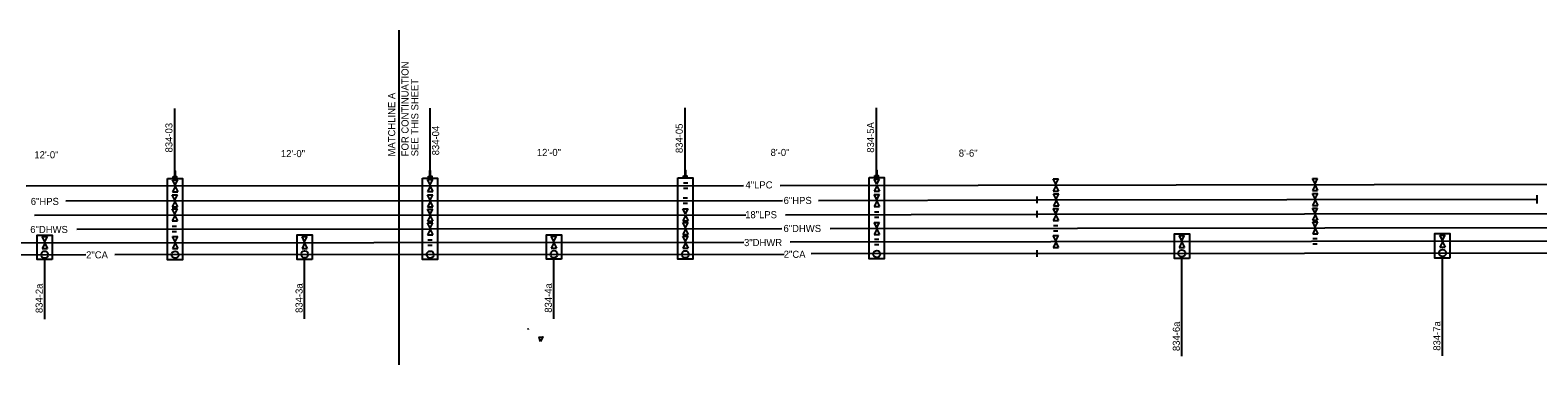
# Model space of a CAD drawing. Extents: x 9888 to 10178, y 10284 to 10314.
# Drawn here: x 10038.1 to 10109, y 10283.8 to 10299.5 of the extents above; entities that cross this region are included whole.
import ezdxf

# ---------------------------------------------------------------- set-up
doc = ezdxf.new("R2010")
doc.units = 0
for name, color, linetype in [('Level 51', 7, 'Continuous'), ('M-ANNO-NPLT', 7, 'Continuous'), ('M-CELL', 7, 'Continuous'), ('M-EQPM-N', 7, 'Continuous'), ('M-STEM-CONP', 7, 'Continuous'), ('M-STEM-CONP-N', 7, 'Continuous'), ('P-CMPA-PIPE', 7, 'Continuous'), ('P-CMPA-PIPE-N', 7, 'Continuous'), ('P-DOMW-HPIP-N', 7, 'Continuous')]:
    doc.layers.add(name, color=color, linetype=linetype)

msp = doc.modelspace()

# ---------------------------------------------------------------- linework, layer by layer
at = {"layer": 'Level 51'}
for p, q in [((10037.895, 10292.216), (10071.644, 10292.241)), ((10044.904, 10292.191), (10044.78, 10291.944)), ((10044.906, 10292.263), (10044.782, 10292.511)), ((10044.782, 10292.511), (10045.03, 10292.511)), ((10044.904, 10292.191), (10045.028, 10291.944)), ((10044.906, 10292.263), (10045.03, 10292.511)), ((10056.902, 10292.268), (10056.778, 10292.516)), ((10056.778, 10292.516), (10057.026, 10292.516)), ((10056.902, 10292.198), (10056.778, 10291.951)), ((10056.902, 10292.268), (10057.026, 10292.516)), ((10056.902, 10292.198), (10057.026, 10291.951)), ((10068.808, 10292.367), (10069.012, 10292.367)), ((10068.808, 10292.117), (10069.012, 10292.117)), ((10073.354, 10292.244), (10142.991, 10292.341)), ((10077.902, 10292.295), (10077.778, 10292.543)), ((10077.778, 10292.543), (10078.026, 10292.543)), ((10077.902, 10292.226), (10077.778, 10291.978)), ((10077.902, 10292.295), (10078.026, 10292.543)), ((10077.902, 10292.226), (10078.026, 10291.978)), ((10086.33, 10292.296), (10086.206, 10292.544)), ((10086.206, 10292.544), (10086.454, 10292.544)), ((10086.33, 10292.227), (10086.206, 10291.979)), ((10086.33, 10292.296), (10086.454, 10292.544)), ((10086.33, 10292.227), (10086.454, 10291.979)), ((10098.518, 10292.318), (10098.394, 10292.566)), ((10098.394, 10292.566), (10098.641, 10292.566)), ((10098.518, 10292.248), (10098.394, 10292.001)), ((10098.518, 10292.318), (10098.641, 10292.566)), ((10098.518, 10292.248), (10098.641, 10292.001)), ((10044.78, 10291.944), (10045.028, 10291.944)), ((10056.778, 10291.951), (10057.026, 10291.951)), ((10077.778, 10291.978), (10078.026, 10291.978)), ((10086.206, 10291.979), (10086.454, 10291.979)), ((10098.394, 10292.001), (10098.641, 10292.001))]:
    msp.add_line(p, q, dxfattribs=at)
at = {"layer": 'M-CELL'}
msp.add_line((10061.531, 10285.442), (10061.505, 10285.51), dxfattribs=at)
msp.add_lwpolyline([(10062.091, 10284.903), (10062.023, 10285.096), (10062.206, 10285.122), (10062.091, 10284.903)], dxfattribs=at)
at = {"layer": 'M-EQPM-N'}
for p, q in [((10044.895, 10292.567), (10044.895, 10295.862)), ((10056.895, 10292.583), (10056.895, 10295.877)), ((10068.895, 10292.598), (10068.895, 10295.893)), ((10077.895, 10292.61), (10077.895, 10295.893)), ((10038.769, 10285.947), (10038.769, 10288.75)), ((10050.995, 10285.957), (10050.995, 10288.759)), ((10062.72, 10285.965), (10062.72, 10288.768)), ((10092.256, 10284.211), (10092.256, 10288.809)), ((10104.51, 10284.228), (10104.51, 10288.825))]:
    msp.add_line(p, q, dxfattribs=at)
for points in [[(10044.542, 10292.567), (10045.247, 10292.567), (10045.247, 10288.743), (10044.542, 10288.743)], [(10056.542, 10292.583), (10057.247, 10292.583), (10057.247, 10288.759), (10056.542, 10288.759)], [(10068.542, 10292.598), (10069.247, 10292.598), (10069.247, 10288.775), (10068.542, 10288.775)], [(10077.542, 10292.61), (10078.247, 10292.61), (10078.247, 10288.786), (10077.542, 10288.786)], [(10039.121, 10288.75), (10038.416, 10288.75), (10038.416, 10289.905), (10039.121, 10289.905)], [(10051.347, 10288.759), (10050.642, 10288.759), (10050.642, 10289.914), (10051.347, 10289.914)], [(10063.072, 10288.768), (10062.367, 10288.768), (10062.367, 10289.923), (10063.072, 10289.923)], [(10092.609, 10288.809), (10091.904, 10288.809), (10091.904, 10289.964), (10092.609, 10289.964)], [(10104.863, 10288.825), (10104.158, 10288.825), (10104.158, 10289.98), (10104.863, 10289.98)]]:
    msp.add_lwpolyline(points, close=True, dxfattribs=at)
at = {"layer": 'M-STEM-CONP'}
for p, q in [((10055.423, 10299.548), (10055.423, 10283.799)), ((10039.757, 10291.511), (10073.463, 10291.537)), ((10044.896, 10291.555), (10044.772, 10291.803)), ((10044.772, 10291.803), (10045.02, 10291.803)), ((10044.896, 10291.485), (10044.772, 10291.238)), ((10044.896, 10291.555), (10045.02, 10291.803)), ((10044.896, 10291.485), (10045.02, 10291.238)), ((10056.902, 10291.545), (10056.778, 10291.793)), ((10056.778, 10291.793), (10057.026, 10291.793)), ((10056.902, 10291.476), (10056.778, 10291.228)), ((10056.902, 10291.545), (10057.026, 10291.793)), ((10056.902, 10291.476), (10057.026, 10291.228)), ((10068.801, 10291.66), (10069.005, 10291.66)), ((10068.801, 10291.41), (10069.005, 10291.41)), ((10075.157, 10291.539), (10085.43, 10291.561)), ((10077.902, 10291.573), (10077.778, 10291.82)), ((10077.778, 10291.82), (10078.026, 10291.82)), ((10077.902, 10291.503), (10077.778, 10291.255)), ((10077.902, 10291.573), (10078.026, 10291.82)), ((10077.902, 10291.503), (10078.026, 10291.255)), ((10085.43, 10291.718), (10085.43, 10291.404)), ((10085.43, 10291.561), (10108.945, 10291.592)), ((10086.337, 10291.597), (10086.213, 10291.845)), ((10086.213, 10291.845), (10086.461, 10291.845)), ((10086.337, 10291.528), (10086.213, 10291.28)), ((10086.337, 10291.597), (10086.461, 10291.845)), ((10086.337, 10291.528), (10086.461, 10291.28)), ((10098.524, 10291.613), (10098.4, 10291.861)), ((10098.4, 10291.861), (10098.648, 10291.861)), ((10098.524, 10291.544), (10098.4, 10291.296)), ((10098.524, 10291.613), (10098.648, 10291.861)), ((10098.524, 10291.544), (10098.648, 10291.296)), ((10108.945, 10291.788), (10108.945, 10291.397)), ((10044.772, 10291.238), (10045.02, 10291.238)), ((10056.778, 10291.228), (10057.026, 10291.228)), ((10077.778, 10291.255), (10078.026, 10291.255)), ((10085.43, 10290.887), (10145.023, 10290.966)), ((10086.329, 10290.914), (10086.205, 10291.162)), ((10086.205, 10291.162), (10086.453, 10291.162)), ((10086.329, 10290.845), (10086.205, 10290.597)), ((10086.213, 10291.28), (10086.461, 10291.28)), ((10086.329, 10290.914), (10086.453, 10291.162)), ((10086.329, 10290.845), (10086.453, 10290.597)), ((10098.4, 10291.296), (10098.648, 10291.296)), ((10086.205, 10290.597), (10086.453, 10290.597))]:
    msp.add_line(p, q, dxfattribs=at)
at = {"layer": 'M-STEM-CONP-N'}
for p, q in [((10038.287, 10290.836), (10071.748, 10290.86)), ((10044.896, 10290.892), (10044.772, 10291.139)), ((10044.772, 10291.139), (10045.02, 10291.139)), ((10044.896, 10290.822), (10044.772, 10290.574)), ((10044.896, 10290.892), (10045.02, 10291.139)), ((10044.896, 10290.822), (10045.02, 10290.574)), ((10056.902, 10290.882), (10056.778, 10291.13)), ((10056.778, 10291.13), (10057.026, 10291.13)), ((10056.902, 10290.813), (10056.778, 10290.565)), ((10056.902, 10290.882), (10057.026, 10291.13)), ((10056.902, 10290.813), (10057.026, 10290.565)), ((10068.902, 10290.898), (10068.778, 10291.145)), ((10068.778, 10291.145), (10069.026, 10291.145)), ((10068.902, 10290.828), (10068.778, 10290.58)), ((10068.902, 10290.898), (10069.026, 10291.145)), ((10068.902, 10290.828), (10069.026, 10290.58)), ((10073.617, 10290.863), (10085.43, 10290.887)), ((10077.792, 10291), (10077.996, 10291)), ((10077.792, 10290.75), (10077.996, 10290.75)), ((10085.43, 10291.04), (10085.43, 10290.727)), ((10098.516, 10290.93), (10098.392, 10291.178)), ((10098.392, 10291.178), (10098.64, 10291.178)), ((10098.516, 10290.861), (10098.392, 10290.613)), ((10098.516, 10290.93), (10098.64, 10291.178)), ((10098.516, 10290.861), (10098.64, 10290.613)), ((10044.772, 10290.574), (10045.02, 10290.574)), ((10056.778, 10290.565), (10057.026, 10290.565)), ((10068.778, 10290.58), (10069.026, 10290.58)), ((10098.392, 10290.613), (10098.64, 10290.613))]:
    msp.add_line(p, q, dxfattribs=at)
at = {"layer": 'P-CMPA-PIPE'}
msp.add_line((10085.43, 10289.037), (10145.135, 10289.116), dxfattribs=at)
for points in [[(10044.874, 10292.671), (10044.921, 10292.671), (10044.921, 10292.907), (10044.874, 10292.907)], [(10056.874, 10292.687), (10056.921, 10292.687), (10056.921, 10292.922), (10056.874, 10292.922)], [(10068.874, 10292.702), (10068.921, 10292.702), (10068.921, 10292.938), (10068.874, 10292.938)], [(10077.874, 10292.714), (10077.921, 10292.714), (10077.921, 10292.949), (10077.874, 10292.949)], [(10044.818, 10292.667), (10044.971, 10292.667), (10044.971, 10292.567), (10044.818, 10292.567)], [(10056.818, 10292.683), (10056.971, 10292.683), (10056.971, 10292.583), (10056.818, 10292.583)], [(10068.818, 10292.698), (10068.971, 10292.698), (10068.971, 10292.598), (10068.818, 10292.598)], [(10077.818, 10292.71), (10077.971, 10292.71), (10077.971, 10292.61), (10077.818, 10292.61)]]:
    msp.add_lwpolyline(points, close=True, dxfattribs=at)
at = {"layer": 'P-CMPA-PIPE-N'}
for p, q in [((9975.124, 10288.884), (10040.708, 10288.99)), ((10042.062, 10288.99), (10073.548, 10289.013)), ((10085.43, 10289.032), (10074.816, 10289.017)), ((10085.43, 10289.189), (10085.43, 10288.876))]:
    msp.add_line(p, q, dxfattribs=at)
for centre in [(10038.77, 10288.987), (10044.904, 10288.981), (10050.996, 10288.996), (10056.902, 10288.988), (10062.721, 10289.005), (10068.902, 10289.004), (10077.902, 10289.015), (10092.257, 10289.046), (10104.511, 10289.062)]:
    msp.add_circle(centre, 0.167, dxfattribs=at)
at = {"layer": 'P-DOMW-HPIP-N'}
for p, q in [((10040.286, 10290.183), (10073.438, 10290.208)), ((10044.769, 10290.33), (10044.973, 10290.33)), ((10044.769, 10290.08), (10044.973, 10290.08)), ((10056.902, 10290.23), (10056.778, 10290.478)), ((10056.778, 10290.478), (10057.026, 10290.478)), ((10056.902, 10290.161), (10056.778, 10289.913)), ((10056.902, 10290.23), (10057.026, 10290.478)), ((10056.902, 10290.161), (10057.026, 10289.913)), ((10068.902, 10290.246), (10068.778, 10290.494)), ((10068.778, 10290.494), (10069.026, 10290.494)), ((10068.902, 10290.176), (10068.778, 10289.929)), ((10068.902, 10290.246), (10069.026, 10290.494)), ((10068.902, 10290.176), (10069.026, 10289.929)), ((10075.709, 10290.221), (10164.791, 10290.337)), ((10077.902, 10290.258), (10077.778, 10290.505)), ((10077.778, 10290.505), (10078.026, 10290.505)), ((10077.902, 10290.188), (10077.778, 10289.94)), ((10077.902, 10290.258), (10078.026, 10290.505)), ((10077.902, 10290.188), (10078.026, 10289.94)), ((10086.224, 10290.36), (10086.428, 10290.36)), ((10086.224, 10290.11), (10086.428, 10290.11)), ((10098.531, 10290.28), (10098.407, 10290.528)), ((10098.407, 10290.528), (10098.654, 10290.528)), ((10098.531, 10290.21), (10098.407, 10289.963)), ((10098.531, 10290.28), (10098.654, 10290.528)), ((10098.531, 10290.21), (10098.654, 10289.963)), ((10036.846, 10289.542), (10071.655, 10289.568)), ((10038.77, 10289.584), (10038.646, 10289.832)), ((10038.646, 10289.832), (10038.894, 10289.832)), ((10038.77, 10289.515), (10038.646, 10289.267)), ((10038.77, 10289.584), (10038.894, 10289.832)), ((10038.77, 10289.515), (10038.894, 10289.267)), ((10044.904, 10289.59), (10044.78, 10289.838)), ((10044.78, 10289.838), (10045.028, 10289.838)), ((10044.904, 10289.521), (10044.78, 10289.273)), ((10044.904, 10289.59), (10045.028, 10289.838)), ((10044.904, 10289.521), (10045.028, 10289.273)), ((10050.996, 10289.594), (10050.872, 10289.841)), ((10050.872, 10289.841), (10051.12, 10289.841)), ((10050.996, 10289.524), (10050.872, 10289.276)), ((10050.996, 10289.594), (10051.12, 10289.841)), ((10050.996, 10289.524), (10051.12, 10289.276)), ((10056.778, 10289.913), (10057.026, 10289.913)), ((10056.791, 10289.684), (10056.995, 10289.684)), ((10056.791, 10289.434), (10056.995, 10289.434)), ((10062.721, 10289.602), (10062.598, 10289.85)), ((10062.598, 10289.85), (10062.845, 10289.85)), ((10062.721, 10289.533), (10062.598, 10289.285)), ((10062.598, 10289.285), (10062.845, 10289.285)), ((10062.721, 10289.602), (10062.845, 10289.85)), ((10062.721, 10289.533), (10062.845, 10289.285)), ((10068.778, 10289.929), (10069.026, 10289.929)), ((10068.914, 10289.601), (10068.79, 10289.849)), ((10068.79, 10289.849), (10069.038, 10289.849)), ((10068.914, 10289.531), (10068.79, 10289.284)), ((10068.79, 10289.284), (10069.038, 10289.284)), ((10068.914, 10289.601), (10069.038, 10289.849)), ((10068.914, 10289.531), (10069.038, 10289.284)), ((10073.838, 10289.582), (10160.703, 10289.695)), ((10077.778, 10289.94), (10078.026, 10289.94)), ((10077.791, 10289.711), (10077.995, 10289.711)), ((10077.791, 10289.461), (10077.995, 10289.461)), ((10086.331, 10289.633), (10086.207, 10289.881)), ((10086.207, 10289.881), (10086.455, 10289.881)), ((10086.331, 10289.564), (10086.207, 10289.316)), ((10086.207, 10289.316), (10086.455, 10289.316)), ((10086.331, 10289.633), (10086.455, 10289.881)), ((10086.331, 10289.564), (10086.455, 10289.316)), ((10092.258, 10289.643), (10092.134, 10289.891)), ((10092.134, 10289.891), (10092.382, 10289.891)), ((10092.258, 10289.574), (10092.134, 10289.326)), ((10092.134, 10289.326), (10092.382, 10289.326)), ((10092.258, 10289.643), (10092.382, 10289.891)), ((10092.258, 10289.574), (10092.382, 10289.326)), ((10098.407, 10289.963), (10098.654, 10289.963)), ((10098.416, 10289.737), (10098.62, 10289.737)), ((10098.416, 10289.487), (10098.62, 10289.487)), ((10104.512, 10289.659), (10104.388, 10289.907)), ((10104.388, 10289.907), (10104.636, 10289.907)), ((10104.512, 10289.59), (10104.388, 10289.342)), ((10104.388, 10289.342), (10104.636, 10289.342)), ((10104.512, 10289.659), (10104.636, 10289.907)), ((10104.512, 10289.59), (10104.636, 10289.342)), ((10038.646, 10289.267), (10038.894, 10289.267)), ((10044.78, 10289.273), (10045.028, 10289.273)), ((10050.872, 10289.276), (10051.12, 10289.276))]:
    msp.add_line(p, q, dxfattribs=at)

# ---------------------------------------------------------------- texts
at = {"layer": 'Level 51'}
msp.add_text('4"LPC', height=0.3333, dxfattribs=at).set_placement((10071.729, 10292.1))
at = {"layer": 'M-ANNO-NPLT'}
for s, p in [('FOR CONTINUATION', (10055.882, 10293.613)), ('SEE THIS SHEET', (10056.346, 10293.613)), ('MATCHLINE A', (10055.255, 10293.604))]:
    msp.add_text(s, height=0.33333, rotation=90, dxfattribs=at).set_placement(p)
at = {"layer": 'M-EQPM-N'}
for s, p in [('834-03', (10044.778, 10293.793)), ('834-04', (10057.323, 10293.658)), ('834-05', (10068.779, 10293.763)), ('834-5A', (10077.779, 10293.781)), ('834-2a', (10038.673, 10286.234)), ('834-3a', (10050.899, 10286.244)), ('834-4a', (10062.624, 10286.253)), ('834-6a', (10092.16, 10284.448)), ('834-7a', (10104.414, 10284.464))]:
    msp.add_text(s, height=0.3333, rotation=90, dxfattribs=at).set_placement(p)
for s, p in [('12\'-0"', (10038.283, 10293.517)), ('12\'-0"', (10049.879, 10293.573)), ('12\'-0"', (10061.917, 10293.628)), ('8\'-0"', (10072.911, 10293.628)), ('8\'-6"', (10081.76, 10293.596))]:
    msp.add_text(s, height=0.3333, dxfattribs=at).set_placement(p)
at = {"layer": 'M-STEM-CONP'}
for p in [(10038.114, 10291.323), (10073.522, 10291.369)]:
    msp.add_text('6"HPS', height=0.3333, dxfattribs=at).set_placement(p)
at = {"layer": 'M-STEM-CONP-N'}
msp.add_text('18"LPS', height=0.3333, dxfattribs=at).set_placement((10071.714, 10290.698))
at = {"layer": 'P-CMPA-PIPE'}
for p in [(10040.717, 10288.809), (10073.528, 10288.835)]:
    msp.add_text('2"CA', height=0.3333, dxfattribs=at).set_placement(p)
at = {"layer": 'P-DOMW-HPIP-N'}
for s, p in [('6"DHWS', (10038.09, 10290.003)), ('6"DHWS', (10073.517, 10290.051)), ('3"DHWR', (10071.661, 10289.387))]:
    msp.add_text(s, height=0.3333, dxfattribs=at).set_placement(p)

doc.saveas('drawing.dxf')
